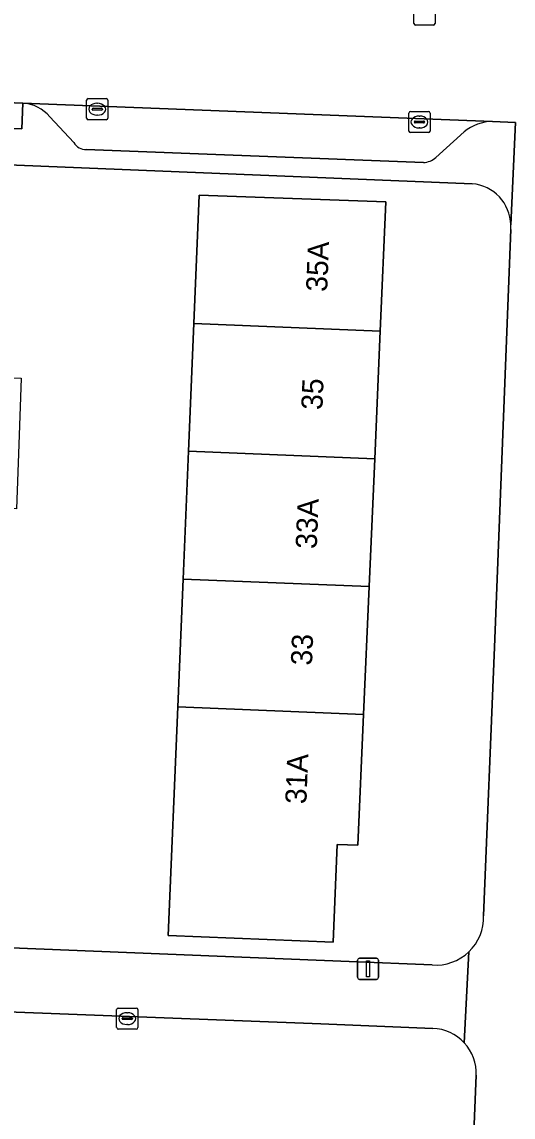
# Model space of a CAD drawing. Extents: x 160732 to 162107, y 387428 to 388479.
# Drawn here: x 161235.9 to 161259.1, y 387662.1 to 387713.9 of the extents above; entities that cross this region are included whole.
import ezdxf

# ---------------------------------------------------------------- set-up
doc = ezdxf.new("R2010")
doc.units = 0
for name, color, linetype in [('IMGEO_Erf', 7, 'Continuous'), ('IMGEO_Kolk', 7, 'Continuous'), ('IMGEO_Lichtmast', 7, 'Continuous'), ('IMGEO_Pand', 7, 'Continuous'), ('IMGEO_Pand_nummerreeks', 7, 'Continuous'), ('IMGEO_Parkeervlak_open', 7, 'Continuous'), ('IMGEO_Rijbaan_lokaal_open', 7, 'Continuous'), ('IMGEO_Voetpad_open', 7, 'Continuous')]:
    doc.layers.add(name, color=color, linetype=linetype)

msp = doc.modelspace()

# ---------------------------------------------------------------- linework, layer by layer
at = {"layer": 'IMGEO_Erf'}
for points in [[(161257.19, 387706.253), (161232.148, 387707.27), (161232.106, 387706.308), (161235.279, 387706.171), (161235.012, 387700.011), (161231.839, 387700.148), (161231.731, 387697.212), (161235.849, 387697.067), (161235.739, 387693.93), (161235.632, 387690.878), (161231.514, 387691.023), (161231.24, 387685.132), (161235.358, 387684.987), (161235.248, 387681.851), (161235.141, 387678.798), (161231.023, 387678.943), (161230.674, 387670.319), (161251.37, 387669.481), (161255.299, 387669.322)], [(161257.727, 387671.649), (161258.24, 387684.343), (161259.011, 387704.09)], [(161255.329, 387666.321), (161250.028, 387666.535), (161230.667, 387667.288)], [(161255.697, 387622.916), (161255.813, 387623.394), (161256.242, 387633.829), (161256.468, 387633.87), (161256.778, 387638.497), (161256.334, 387638.507), (161257.384, 387664.107)]]:
    msp.add_lwpolyline(points, dxfattribs=at)
msp.add_lwpolyline([(161243.761, 387693.605), (161244.013, 387699.645), (161244.267, 387705.717), (161253.107, 387705.39), (161252.841, 387699.286), (161252.579, 387693.248), (161252.316, 387687.208), (161252.054, 387681.168), (161251.785, 387674.98), (161250.806, 387675.02), (161250.619, 387670.404), (161242.805, 387670.722), (161243.256, 387681.526), (161243.509, 387687.565)], close=True, dxfattribs=at)
for centre, radius, start, end in [((161257.011, 387704.255), 2.006, 1.376, 84.8936), ((161257.132, 387704.25), 1.885, 355.1468, 1.6262), ((161255.465, 387671.579), 2.264, 313.7919, 1.7729), ((161255.467, 387671.575), 2.259, 265.7444, 313.8229), ((161255.252, 387664.187), 2.136, 42.9195, 87.9316), ((161255.255, 387664.191), 2.13, 357.7396, 42.897)]:
    msp.add_arc(centre, radius, start, end, dxfattribs=at)
at = {"layer": 'IMGEO_Kolk'}
for p, q in [((161254.432, 387713.824), (161254.432, 387714.676)), ((161255.433, 387714.676), (161255.433, 387713.824)), ((161255.359, 387713.75), (161254.507, 387713.75)), ((161238.95, 387709.349), (161238.95, 387710.201)), ((161239.025, 387710.275), (161239.877, 387710.275)), ((161239.438, 387710.055), (161239.463, 387710.055)), ((161239.951, 387710.201), (161239.951, 387709.349)), ((161239.209, 387709.769), (161239.209, 387709.781)), ((161239.647, 387709.732), (161239.249, 387709.732)), ((161239.252, 387709.818), (161239.65, 387709.818)), ((161239.461, 387709.495), (161239.436, 387709.495)), ((161239.693, 387709.781), (161239.693, 387709.769)), ((161254.194, 387708.744), (161254.194, 387709.596)), ((161254.269, 387709.67), (161255.121, 387709.67)), ((161254.682, 387709.45), (161254.707, 387709.45)), ((161255.195, 387709.596), (161255.195, 387708.744)), ((161239.877, 387709.275), (161239.025, 387709.275)), ((161254.453, 387709.164), (161254.453, 387709.176)), ((161254.891, 387709.127), (161254.493, 387709.127)), ((161254.496, 387709.213), (161254.894, 387709.213)), ((161254.705, 387708.89), (161254.68, 387708.89)), ((161254.937, 387709.176), (161254.937, 387709.164)), ((161255.121, 387708.67), (161254.269, 387708.67)), ((161240.37, 387666.361), (161240.37, 387667.213)), ((161240.445, 387667.287), (161241.297, 387667.287)), ((161240.858, 387667.067), (161240.883, 387667.067)), ((161241.371, 387667.213), (161241.371, 387666.361)), ((161240.629, 387666.781), (161240.629, 387666.793)), ((161241.067, 387666.744), (161240.669, 387666.744)), ((161240.672, 387666.83), (161241.07, 387666.83)), ((161240.881, 387666.507), (161240.856, 387666.507)), ((161241.113, 387666.793), (161241.113, 387666.781)), ((161241.297, 387666.287), (161240.445, 387666.287))]:
    msp.add_line(p, q, dxfattribs=at)
for points in [[(161254.432, 387713.824), (161254.432, 387714.676)], [(161255.433, 387714.676), (161255.433, 387713.824)], [(161255.359, 387713.75), (161254.507, 387713.75)], [(161238.95, 387709.349), (161238.95, 387710.201)], [(161239.025, 387710.275), (161239.877, 387710.275)], [(161239.951, 387710.201), (161239.951, 387709.349)], [(161254.194, 387708.744), (161254.194, 387709.596)], [(161254.269, 387709.67), (161255.121, 387709.67)], [(161255.195, 387709.596), (161255.195, 387708.744)], [(161239.877, 387709.275), (161239.025, 387709.275)], [(161255.121, 387708.67), (161254.269, 387708.67)], [(161240.37, 387666.361), (161240.37, 387667.213)], [(161240.445, 387667.287), (161241.297, 387667.287)], [(161241.371, 387667.213), (161241.371, 387666.361)], [(161241.297, 387666.287), (161240.445, 387666.287)]]:
    msp.add_lwpolyline(points, dxfattribs=at)
for centre, radius, start, end in [((161254.509, 387713.826), 0.0765, 181.552, 268.448), ((161254.509, 387713.826), 0.0765, 181.552, 268.448), ((161255.357, 387713.826), 0.0765, 271.552, 358.448), ((161255.357, 387713.826), 0.0765, 271.552, 358.448), ((161239.027, 387710.199), 0.0765, 91.552, 178.448), ((161239.027, 387710.199), 0.0765, 91.552, 178.448), ((161239.875, 387710.199), 0.0765, 1.552, 88.448), ((161239.875, 387710.199), 0.0765, 1.552, 88.448), ((161239.249, 387709.778), 0.0403, 85.8775, 175.7526), ((161239.246, 387709.768), 0.0366, 178.938, 274.7102), ((161239.65, 387709.775), 0.043, 264.8664, 352.4533), ((161239.654, 387709.78), 0.0386, 1.7309, 96.639), ((161254.271, 387709.594), 0.0765, 91.552, 178.448), ((161254.271, 387709.594), 0.0765, 91.552, 178.448), ((161255.119, 387709.594), 0.0765, 1.552, 88.448), ((161255.119, 387709.594), 0.0765, 1.552, 88.448), ((161239.027, 387709.351), 0.0765, 181.552, 268.448), ((161239.027, 387709.351), 0.0765, 181.552, 268.448), ((161239.875, 387709.351), 0.0765, 271.552, 358.448), ((161239.875, 387709.351), 0.0765, 271.552, 358.448), ((161254.493, 387709.173), 0.0403, 85.8775, 175.7526), ((161254.49, 387709.163), 0.0366, 178.938, 274.7102), ((161254.894, 387709.17), 0.043, 264.8664, 352.4533), ((161254.898, 387709.175), 0.0386, 1.7309, 96.639), ((161254.271, 387708.746), 0.0765, 181.552, 268.448), ((161254.271, 387708.746), 0.0765, 181.552, 268.448), ((161255.119, 387708.746), 0.0765, 271.552, 358.448), ((161255.119, 387708.746), 0.0765, 271.552, 358.448), ((161240.447, 387667.211), 0.0765, 91.552, 178.448), ((161240.447, 387667.211), 0.0765, 91.552, 178.448), ((161241.295, 387667.211), 0.0765, 1.552, 88.448), ((161241.295, 387667.211), 0.0765, 1.552, 88.448), ((161240.669, 387666.79), 0.0403, 85.8775, 175.7526), ((161240.666, 387666.78), 0.0366, 178.938, 274.7102), ((161241.07, 387666.787), 0.043, 264.8664, 352.4533), ((161241.074, 387666.792), 0.0386, 1.7309, 96.639), ((161240.447, 387666.363), 0.0765, 181.552, 268.448), ((161240.447, 387666.363), 0.0765, 181.552, 268.448), ((161241.295, 387666.363), 0.0765, 271.552, 358.448), ((161241.295, 387666.363), 0.0765, 271.552, 358.448)]:
    msp.add_arc(centre, radius, start, end, dxfattribs=at)
for centre, major_axis, ratio, start_param, end_param in [((161239.437, 387709.775), (-0.387, 0.002), 0.722429, 4.712389, 7.853982), ((161239.462, 387709.775), (-0.39, 0.002), 0.717154, 1.570796, 4.712389), ((161254.681, 387709.17), (-0.387, 0.002), 0.722429, 4.712389, 7.853982), ((161254.706, 387709.17), (-0.39, 0.002), 0.717154, 1.570796, 4.712389), ((161240.857, 387666.787), (-0.387, 0.002), 0.722429, 4.712389, 7.853982), ((161240.882, 387666.787), (-0.39, 0.002), 0.717154, 1.570796, 4.712389)]:
    msp.add_ellipse(centre, major_axis=major_axis, ratio=ratio, start_param=start_param, end_param=end_param, dxfattribs=at)
at = {"layer": 'IMGEO_Lichtmast'}
for p, q in [((161251.765, 387668.744), (161251.765, 387669.544)), ((161251.765, 387669.544), (161251.765, 387668.744)), ((161251.865, 387669.644), (161252.655, 387669.644)), ((161252.655, 387669.644), (161251.865, 387669.644)), ((161252.755, 387669.544), (161252.755, 387668.744)), ((161252.755, 387668.744), (161252.755, 387669.544)), ((161252.655, 387668.644), (161251.865, 387668.644)), ((161251.865, 387668.644), (161252.655, 387668.644))]:
    msp.add_line(p, q, dxfattribs=at)
msp.add_lwpolyline([(161252.185, 387669.519), (161252.335, 387669.519), (161252.335, 387668.769), (161252.185, 387668.769), (161252.185, 387669.519)], dxfattribs=at)
for centre, start, end in [((161251.865, 387669.544), 90, 180), ((161251.865, 387669.544), 90, 180), ((161252.655, 387669.544), 0, 90), ((161252.655, 387669.544), 360, 90), ((161251.865, 387668.744), 180, 270), ((161251.865, 387668.744), 180, 270), ((161252.655, 387668.744), 270, 0), ((161252.655, 387668.744), 270, 0)]:
    msp.add_arc(centre, 0.1, start, end, dxfattribs=at)
at = {"layer": 'IMGEO_Pand'}
for points in [[(161253.107, 387705.39), (161244.267, 387705.717), (161244.013, 387699.645), (161252.841, 387699.286)], [(161252.841, 387699.286), (161244.013, 387699.645), (161243.761, 387693.605), (161252.579, 387693.248)], [(161252.579, 387693.248), (161243.761, 387693.605), (161243.509, 387687.565), (161252.316, 387687.208)], [(161252.316, 387687.208), (161243.509, 387687.565), (161243.256, 387681.526), (161252.054, 387681.168)], [(161252.054, 387681.168), (161243.256, 387681.526), (161242.805, 387670.722), (161250.619, 387670.404), (161250.806, 387675.02), (161251.785, 387674.98)]]:
    msp.add_lwpolyline(points, close=True, dxfattribs=at)
at = {"layer": 'IMGEO_Parkeervlak_open'}
for points in [[(161258.15, 387709.198), (161235.923, 387710.068)], [(161237.209, 387709.418), (161238.344, 387708.194)], [(161255.471, 387707.497), (161256.812, 387708.712)], [(161238.93, 387707.865), (161254.883, 387707.253)]]:
    msp.add_lwpolyline(points, dxfattribs=at)
for centre, radius, start, end in [((161235.793, 387708.214), 1.858, 40.3751, 85.9969), ((161258.2, 387706.976), 2.223, 91.2855, 128.6394), ((161238.936, 387708.562), 0.697, 211.8503, 269.5271), ((161254.836, 387708.198), 0.946, 272.8764, 312.1972)]:
    msp.add_arc(centre, radius, start, end, dxfattribs=at)
at = {"layer": 'IMGEO_Rijbaan_lokaal_open'}
msp.add_lwpolyline([(161231.579, 387715.221), (161192.747, 387716.82), (161166.782, 387717.863), (161166.569, 387712.818), (161190.77, 387711.86), (161192.634, 387711.802), (161235.923, 387710.068), (161258.15, 387709.198), (161259.239, 387709.146)], dxfattribs=at)
at = {"layer": 'IMGEO_Voetpad_open'}
for points in [[(161117.208, 387713.432), (161158.739, 387711.663), (161158.67, 387710.144), (161163.496, 387709.962), (161191.658, 387708.973), (161191.897, 387708.965), (161191.909, 387708.829), (161193.233, 387708.84), (161196.908, 387708.68), (161200.582, 387708.52), (161203.285, 387708.434), (161206.919, 387708.292), (161210.556, 387708.15), (161213.329, 387708.047), (161216.973, 387707.894), (161220.62, 387707.741), (161223.404, 387707.611), (161227.007, 387707.472), (161230.61, 387707.332), (161232.148, 387707.27), (161257.19, 387706.253)], [(161235.923, 387710.068), (161235.884, 387708.849), (161214.515, 387709.704), (161192.586, 387710.609)], [(161238.344, 387708.194), (161237.209, 387709.418)], [(161259.017, 387704.303), (161259.239, 387709.146), (161258.15, 387709.198)], [(161259.239, 387709.146), (161259.017, 387704.303)], [(161256.812, 387708.712), (161255.471, 387707.497)], [(161254.883, 387707.253), (161238.93, 387707.865)], [(161259.011, 387704.09), (161258.24, 387684.343), (161257.727, 387671.649)], [(161255.299, 387669.322), (161251.37, 387669.481), (161230.674, 387670.319), (161229.173, 387670.38), (161191.731, 387671.897), (161190.216, 387671.958), (161167.298, 387672.886)], [(161167.1, 387669.761), (161190.137, 387668.865), (161191.672, 387668.805), (161229.173, 387667.346), (161230.667, 387667.288), (161250.028, 387666.535), (161255.329, 387666.321)], [(161256.816, 387665.641), (161257.031, 387669.945)], [(161257.031, 387669.945), (161256.816, 387665.641)], [(161257.384, 387664.107), (161256.334, 387638.507), (161256.778, 387638.497), (161256.468, 387633.87), (161256.242, 387633.829), (161255.813, 387623.394), (161255.697, 387622.916)]]:
    msp.add_lwpolyline(points, dxfattribs=at)
msp.add_lwpolyline([(161192.634, 387711.802), (161192.586, 387710.609), (161214.515, 387709.704), (161235.884, 387708.849), (161235.923, 387710.068)], close=True, dxfattribs=at)
for centre, radius, start, end in [((161235.793, 387708.214), 1.858, 40.3751, 85.9969), ((161258.2, 387706.976), 2.223, 91.2855, 128.6394), ((161238.936, 387708.562), 0.697, 211.8503, 269.5271), ((161254.836, 387708.198), 0.946, 272.8764, 312.1972), ((161257.011, 387704.255), 2.006, 1.376, 84.8936), ((161257.132, 387704.25), 1.885, 355.1468, 1.6262), ((161255.465, 387671.579), 2.264, 313.7919, 1.7729), ((161255.467, 387671.575), 2.259, 265.7444, 313.8229), ((161255.252, 387664.187), 2.136, 42.9195, 87.9316), ((161255.255, 387664.191), 2.13, 357.7396, 42.897)]:
    msp.add_arc(centre, radius, start, end, dxfattribs=at)

# ---------------------------------------------------------------- texts
at = {"layer": 'IMGEO_Pand_nummerreeks'}
for s, p in [('35A', (161250.327, 387701.132)), ('35', (161250.1, 387695.546)), ('33A', (161249.833, 387688.976)), ('33', (161249.608, 387683.466)), ('31A', (161249.342, 387676.913))]:
    msp.add_text(s, height=1, rotation=87.6701, dxfattribs=at).set_placement(p)

doc.saveas('drawing.dxf')
